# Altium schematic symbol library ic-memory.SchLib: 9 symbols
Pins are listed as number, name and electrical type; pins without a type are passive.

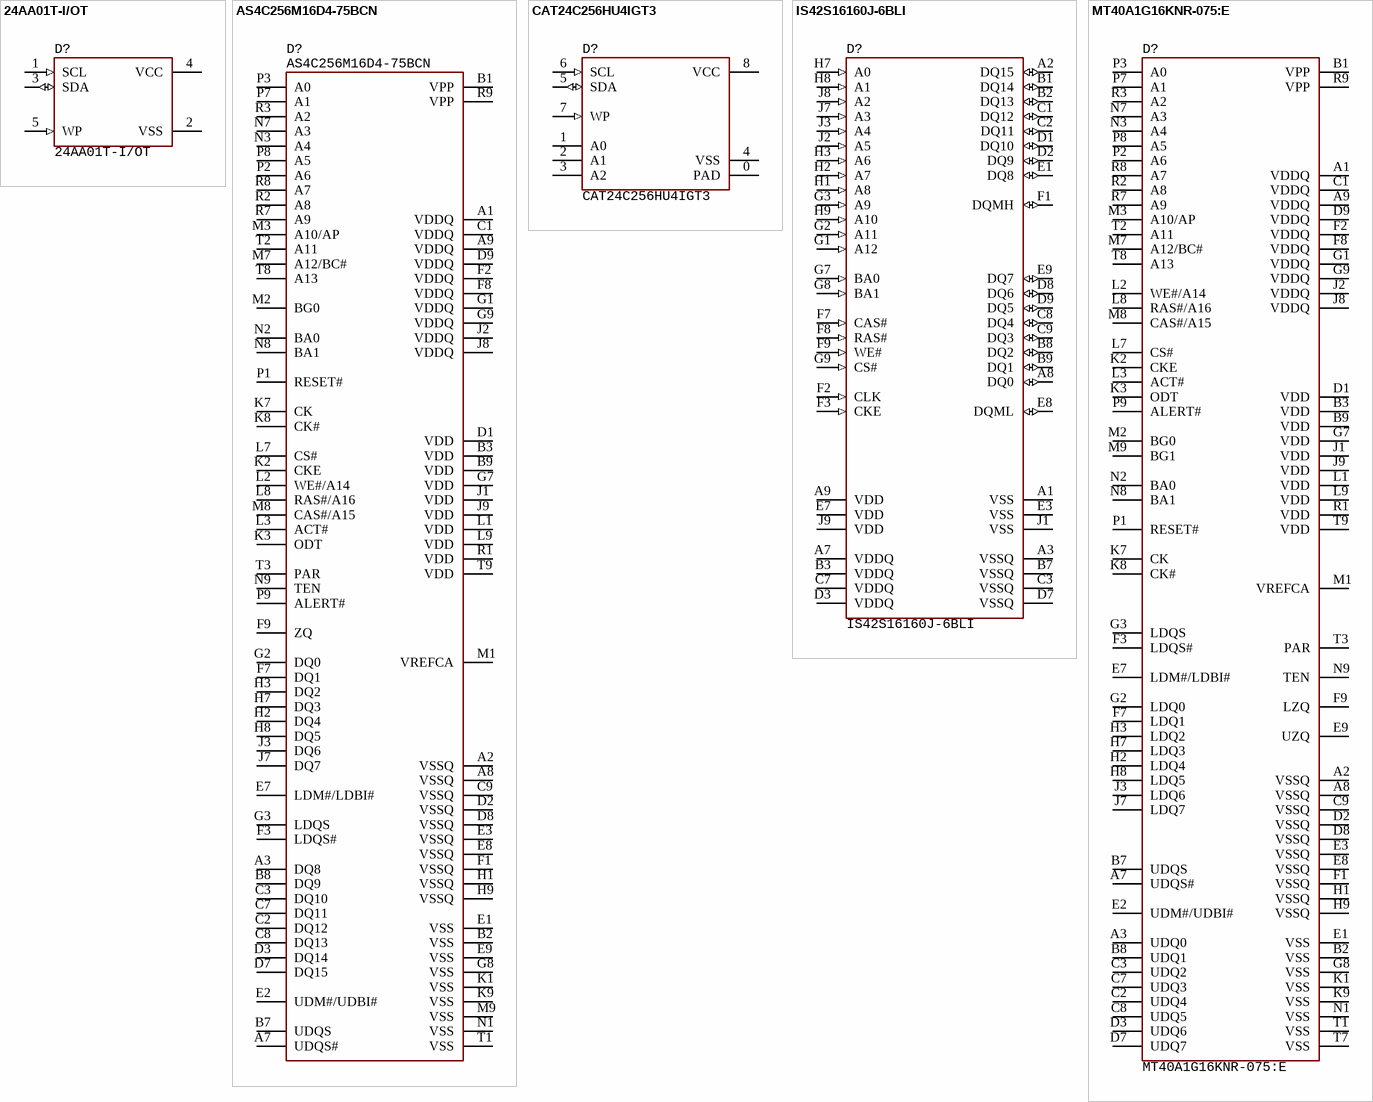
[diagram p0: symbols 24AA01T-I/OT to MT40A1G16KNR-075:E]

## 24AA01T-I/OT
designator D?
EEPROM, 1KB (128x8), I2C, 100kHz, supply 1.7...5.5V, SOT-23-5, -40...+85°C; Manufacturer: Microchip
footprint SOT23-5 (pitch 0.95 mm)
pins: 1 SCL (in), 2 VSS (power), 3 SDA (io), 4 VCC (power), 5 WP (in)

## AS4C256M16D4-75BCN
designator D?
DDR4 SDRAM, 4Gbit, 2666 MT/s, supply 1.14...1.26V, FBGA-96, 0...+95°C; Manufacture: Alliance Memory
footprint 96-FBGA (13.5x7.5, pitch 0.8) (pitch 0.8mm)
pins: A1 VDDQ, A2 VSSQ, A3 DQ8, A7 UDQS#, A8 VSSQ, A9 VDDQ, B1 VPP, B2 VSS, B3 VDD, B7 UDQS, B8 DQ9, B9 VDD, C1 VDDQ, C2 DQ12, C3 DQ10, C7 DQ11, C8 DQ13, C9 VSSQ, D1 VDD, D2 VSSQ, D3 DQ14, D7 DQ15, D8 VSSQ, D9 VDDQ, E1 VSS, E2 UDM#/UDBI#, E3 VSSQ, E7 LDM#/LDBI#, E8 VSSQ, E9 VSS, F1 VSSQ, F2 VDDQ, F3 LDQS#, F7 DQ1, F8 VDDQ, F9 ZQ, G1 VDDQ, G2 DQ0, G3 LDQS, G7 VDD, G8 VSS, G9 VDDQ, H1 VSSQ, H2 DQ4, H3 DQ2, H7 DQ3, H8 DQ5, H9 VSSQ, J1 VDD, J2 VDDQ, J3 DQ6, J7 DQ7, J8 VDDQ, J9 VDD, K1 VSS, K2 CKE, K3 ODT, K7 CK, K8 CK#, K9 VSS, L1 VDD, L2 WE#/A14, L3 ACT#, L7 CS#, L8 RAS#/A16, L9 VDD, M1 VREFCA, M2 BG0, M3 A10/AP, M7 A12/BC#, M8 CAS#/A15, M9 VSS, N1 VSS, N2 BA0, N3 A4, N7 A3, N8 BA1, N9 TEN, P1 RESET#, P2 A6, P3 A0, P7 A1, P8 A5, P9 ALERT#, R1 VDD, R2 A8, R3 A2, R7 A9, R8 A7, R9 VPP, T1 VSS, T2 A11, T3 PAR, T8 A13, T9 VDD

## CAT24C256HU4IGT3
designator D?
EEPROM, 256Kb (32K x 8), I2C, 1MHz, supply 1.8...5.5V, UDFN-8, -40...+85°C; Manufacturer: ON Semiconductor
footprint 8-DFN (2x3, 0.5 mm)
pins: 0 PAD, 1 A0, 2 A1, 3 A2, 4 VSS, 5 SDA (io), 6 SCL (in), 7 WP (in), 8 VCC

## IS42S16160J-6BLI
designator D?  PartNumber: IS42S16160J-6BLI
SDRAM, 256 Mbit, 166 MHz, suplly 3...3.6V, 0...+95°C, 96-TFBGA; Manufacturer: ISSI
footprint 54-TFBGA (8x8, pitch 0.8)
pins: A1 VSS, A2 DQ15 (io), A3 VSSQ, A7 VDDQ, A8 DQ0 (io), A9 VDD, B1 DQ14 (io), B2 DQ13 (io), B3 VDDQ, B7 VSSQ, B8 DQ2 (io), B9 DQ1 (io), C1 DQ12 (io), C2 DQ11 (io), C3 VSSQ, C7 VDDQ, C8 DQ4 (io), C9 DQ3 (io), D1 DQ10 (io), D2 DQ9 (io), D3 VDDQ, D7 VSSQ, D8 DQ6 (io), D9 DQ5 (io), E1 DQ8 (io), E3 VSS, E7 VDD, E8 DQML (io), E9 DQ7 (io), F1 DQMH (io), F2 CLK (in), F3 CKE (in), F7 CAS# (in), F8 RAS# (in), F9 WE# (in), G1 A12 (in), G2 A11 (in), G3 A9 (in), G7 BA0 (in), G8 BA1 (in), G9 CS# (in), H1 A8 (in), H2 A7 (in), H3 A6 (in), H7 A0 (in), H8 A1 (in), H9 A10 (in), J1 VSS, J2 A5 (in), J3 A4 (in), J7 A3 (in), J8 A2 (in), J9 VDD

## MT40A1G16KNR-075:E
designator D?
DDR4 SDRAM, 16G (1G x 16), 3200 MT/s, supply 1.14...1.26V, FBGA-96, 0...+95°C; Manufacturer: Micron; Manufacturer: Micron Technology
footprint 96-FBGA (13.5x7.5, pitch 0.8) (pitch 0.8mm)
pins: A1 VDDQ, A2 VSSQ, A3 UDQ0, A7 UDQS#, A8 VSSQ, A9 VDDQ, B1 VPP, B2 VSS, B3 VDD, B7 UDQS, B8 UDQ1, B9 VDD, C1 VDDQ, C2 UDQ4, C3 UDQ2, C7 UDQ3, C8 UDQ5, C9 VSSQ, D1 VDD, D2 VSSQ, D3 UDQ6, D7 UDQ7, D8 VSSQ, D9 VDDQ, E1 VSS, E2 UDM#/UDBI#, E3 VSSQ, E7 LDM#/LDBI#, E8 VSSQ, E9 UZQ, F1 VSSQ, F2 VDDQ, F3 LDQS#, F7 LDQ1, F8 VDDQ, F9 LZQ, G1 VDDQ, G2 LDQ0, G3 LDQS, G7 VDD, G8 VSS, G9 VDDQ, H1 VSSQ, H2 LDQ4, H3 LDQ2, H7 LDQ3, H8 LDQ5, H9 VSSQ, J1 VDD, J2 VDDQ, J3 LDQ6, J7 LDQ7, J8 VDDQ, J9 VDD, K1 VSS, K2 CKE, K3 ODT, K7 CK, K8 CK#, K9 VSS, L1 VDD, L2 WE#/A14, L3 ACT#, L7 CS#, L8 RAS#/A16, L9 VDD, M1 VREFCA, M2 BG0, M3 A10/AP, M7 A12/BC#, M8 CAS#/A15, M9 BG1, N1 VSS, N2 BA0, N3 A4, N7 A3, N8 BA1, N9 TEN, P1 RESET#, P2 A6, P3 A0, P7 A1, P8 A5, P9 ALERT#, R1 VDD, R2 A8, R3 A2, R7 A9, R8 A7, R9 VPP, T1 VSS, T2 A11, T3 PAR, T7 VSS, T8 A13, T9 VDD

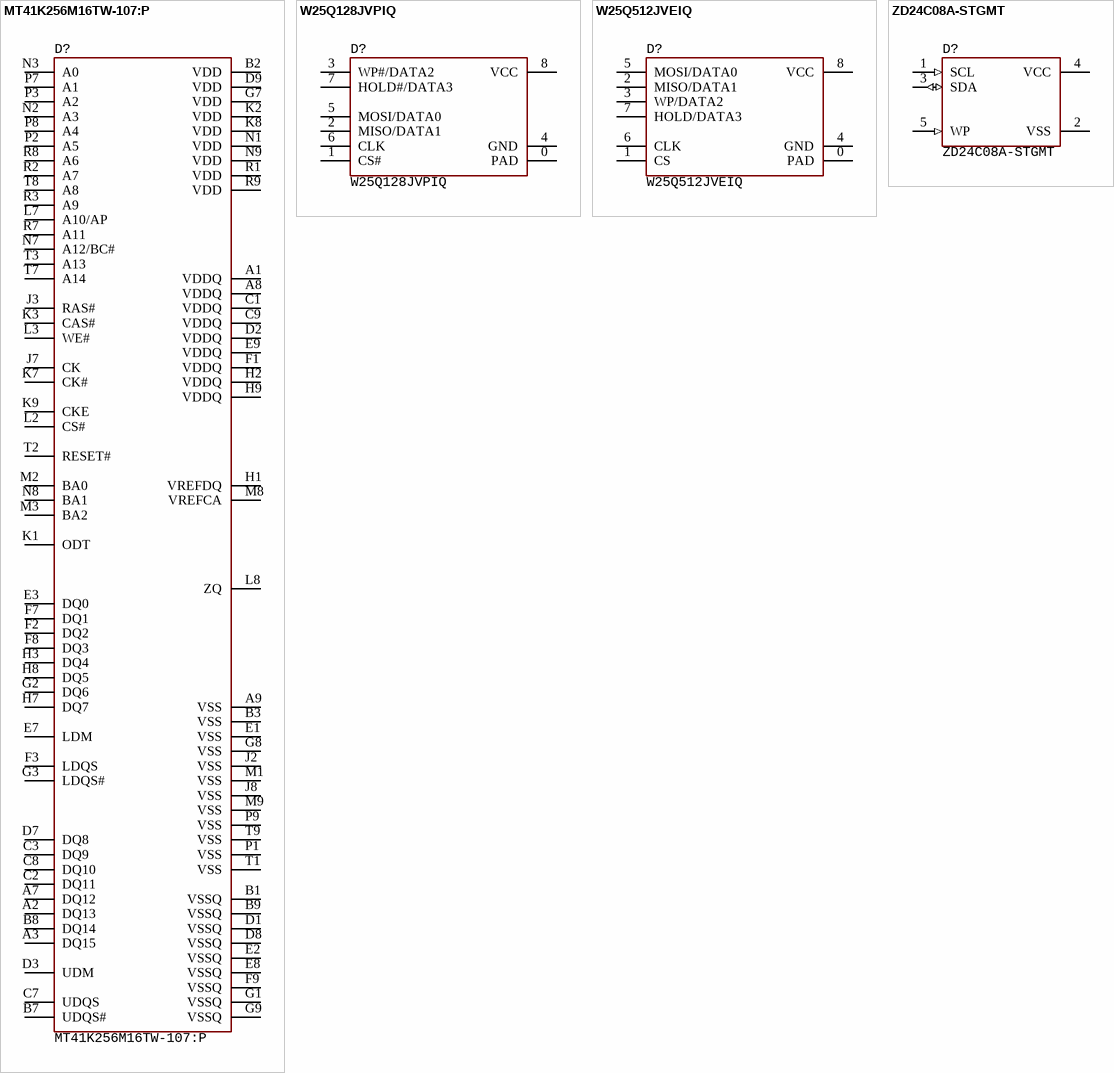
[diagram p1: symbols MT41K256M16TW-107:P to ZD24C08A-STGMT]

## MT41K256M16TW-107:P
designator D?  PartNumber: MT41K256M16TW-107:P
DDR3, 4 Gbit, 1866 MT/s, suplly 1.425...1.575V, 0...+95°C, 96-TFBGA; Manufacturer: Micron
footprint 96-TFBGA (14x8, pitch 0.8) (pitch 0.8mm)
pins: A1 VDDQ, A2 DQ13, A3 DQ15, A7 DQ12, A8 VDDQ, A9 VSS, B1 VSSQ, B2 VDD, B3 VSS, B7 UDQS#, B8 DQ14, B9 VSSQ, C1 VDDQ, C2 DQ11, C3 DQ9, C7 UDQS, C8 DQ10, C9 VDDQ, D1 VSSQ, D2 VDDQ, D3 UDM, D7 DQ8, D8 VSSQ, D9 VDD, E1 VSS, E2 VSSQ, E3 DQ0, E7 LDM, E8 VSSQ, E9 VDDQ, F1 VDDQ, F2 DQ2, F3 LDQS, F7 DQ1, F8 DQ3, F9 VSSQ, G1 VSSQ, G2 DQ6, G3 LDQS#, G7 VDD, G8 VSS, G9 VSSQ, H1 VREFDQ, H2 VDDQ, H3 DQ4, H7 DQ7, H8 DQ5, H9 VDDQ, J2 VSS, J3 RAS#, J7 CK, J8 VSS, K1 ODT, K2 VDD, K3 CAS#, K7 CK#, K8 VDD, K9 CKE, L2 CS#, L3 WE#, L7 A10/AP, L8 ZQ, M1 VSS, M2 BA0, M3 BA2, M8 VREFCA, M9 VSS, N1 VDD, N2 A3, N3 A0, N7 A12/BC#, N8 BA1, N9 VDD, P1 VSS, P2 A5, P3 A2, P7 A1, P8 A4, P9 VSS, R1 VDD, R2 A7, R3 A9, R7 A11, R8 A6, R9 VDD, T1 VSS, T2 RESET#, T3 A13, T7 A14, T8 A8, T9 VSS

## W25Q128JVPIQ
designator D?
NOR FLASH, 128Mb (16M x 8b), QSPI, 133 MHz, supply 2.7...3.6V, WSON-8, -40...+85°C; Manufacturer: Winbond
footprint 8-DFN (5x6, 1.27 mm) (5x6 mm, pitch 1.27 mm, power pad)
pins: 0 PAD, 1 CS#, 2 MISO/DATA1, 3 WP#/DATA2, 4 GND, 5 MOSI/DATA0, 6 CLK, 7 HOLD#/DATA3, 8 VCC

## W25Q512JVEIQ
designator D?
NOR FLASH, 512 Mbit (64M x 8b), QuadSPI, 133 MHz, supply 2.7...3.6V, WSON-8, -40...+85°C; Manufacturer: Winbond
footprint 8-DFN (8x6, 1.27 mm) (8x6 mm, pitch 1.27 mm, power pad)
pins: 0 PAD, 1 CS, 2 MISO/DATA1, 3 WP/DATA2, 4 GND, 5 MOSI/DATA0, 6 CLK, 7 HOLD/DATA3, 8 VCC

## ZD24C08A-STGMT
designator D?
EEPROM, 8KB (1024x8), I2C, 1MHz, supply 1.7...5.5V, SOT-23-5, -40...+85°C; Manufacturer: Zetta
footprint SOT23-5 (pitch 0.95 mm)
pins: 1 SCL (in), 2 VSS (power), 3 SDA (io), 4 VCC (power), 5 WP (in)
